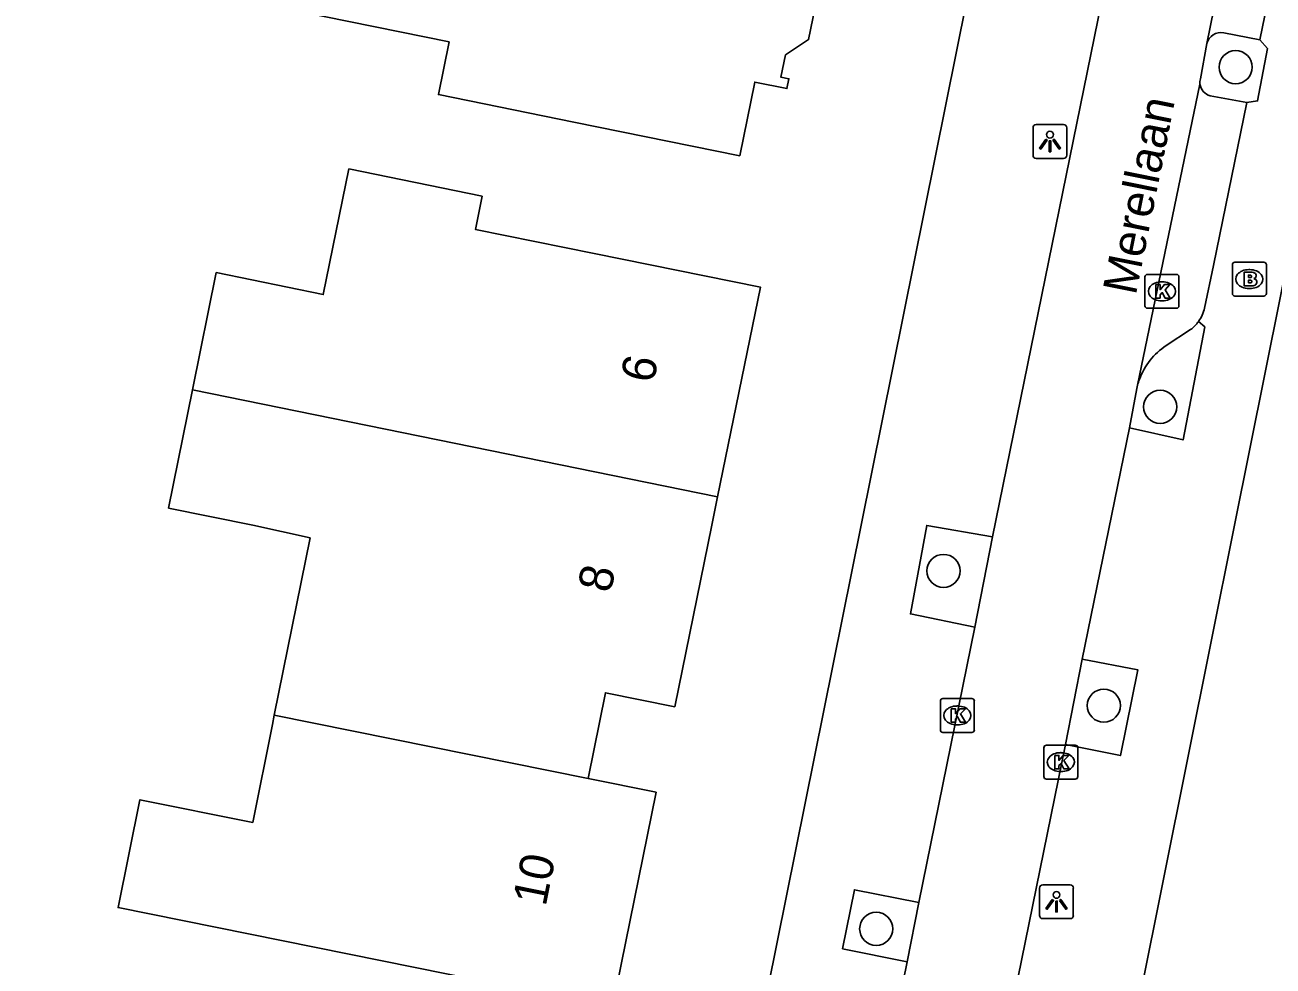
# Model space of a CAD drawing. Extents: x 161772 to 163123, y 383092 to 383917.
# Drawn here: x 162228.47 to 162265.29, y 383736.99 to 383764.76 of the extents above; entities that cross this region are included whole.
import ezdxf

# ---------------------------------------------------------------- set-up
doc = ezdxf.new("R2010")
doc.units = 0
for name, color, linetype in [('IMGEO_Boom', 7, 'Continuous'), ('IMGEO_Brandkraan', 7, 'Continuous'), ('IMGEO_Kolk', 7, 'Continuous'), ('IMGEO_Lichtpunt', 7, 'Continuous'), ('IMGEO_Openbare_ruimte_label', 7, 'Continuous'), ('IMGEO_Pand', 7, 'Continuous'), ('IMGEO_Pand_nummerreeks', 7, 'Continuous'), ('IMGEO_Parkeervlak_open', 7, 'Continuous'), ('IMGEO_Rijbaan_lokaal_open', 7, 'Continuous'), ('IMGEO_Voetpad_open', 7, 'Continuous')]:
    doc.layers.add(name, color=color, linetype=linetype)

msp = doc.modelspace()

# ---------------------------------------------------------------- linework, layer by layer
at = {"layer": 'IMGEO_Boom'}
for centre in [(162264.182, 383763.515), (162261.957, 383753.491), (162255.565, 383748.65), (162260.294, 383744.676), (162253.582, 383738.089)]:
    msp.add_circle(centre, 0.489, dxfattribs=at)
at = {"layer": 'IMGEO_Brandkraan'}
for p, q in [((162264.087, 383756.834), (162264.087, 383757.686)), ((162264.162, 383757.76), (162265.014, 383757.76)), ((162264.575, 383757.54), (162264.6, 383757.54)), ((162265.088, 383757.686), (162265.088, 383756.834)), ((162265.014, 383756.76), (162264.162, 383756.76)), ((162264.598, 383756.98), (162264.573, 383756.98))]:
    msp.add_line(p, q, dxfattribs=at)
for points in [[(162264.087, 383756.834), (162264.087, 383757.686)], [(162264.162, 383757.76), (162265.014, 383757.76)], [(162264.435, 383757.46), (162264.435, 383757.06), (162264.648, 383757.06)], [(162264.666, 383757.46), (162264.435, 383757.46)], [(162265.088, 383757.686), (162265.088, 383756.834)], [(162264.614, 383757.379), (162264.56, 383757.379), (162264.56, 383757.303)], [(162264.56, 383757.303), (162264.613, 383757.303)], [(162264.622, 383757.227), (162264.56, 383757.227), (162264.56, 383757.146)], [(162264.56, 383757.146), (162264.622, 383757.146)], [(162265.014, 383756.76), (162264.162, 383756.76)]]:
    msp.add_lwpolyline(points, dxfattribs=at)
for centre, radius, start, end in [((162264.164, 383757.684), 0.0765, 91.552, 178.448), ((162264.164, 383757.684), 0.0765, 91.552, 178.448), ((162264.67, 383757.315), 0.145, 59.4692, 91.5367), ((162265.012, 383757.684), 0.0765, 1.552, 88.448), ((162265.012, 383757.684), 0.0765, 1.552, 88.448), ((162264.615, 383757.341), 0.0379, 267.8285, 90.9355), ((162264.623, 383757.186), 0.0404, 269.8759, 90.5077), ((162264.695, 383757.362), 0.0922, 285.5137, 58.1501), ((162264.7, 383757.17), 0.105, 301.3115, 78.989), ((162264.164, 383756.836), 0.0765, 181.552, 268.448), ((162264.164, 383756.836), 0.0765, 181.552, 268.448), ((162264.654, 383757.311), 0.251, 268.6676, 293.5347), ((162265.012, 383756.836), 0.0765, 271.552, 358.448), ((162265.012, 383756.836), 0.0765, 271.552, 358.448)]:
    msp.add_arc(centre, radius, start, end, dxfattribs=at)
for centre, major_axis, ratio, start_param, end_param in [((162264.574, 383757.26), (-0.387, 0.002), 0.722429, 4.712389, 7.853982), ((162264.599, 383757.26), (-0.39, 0.002), 0.717154, 1.570796, 4.712389)]:
    msp.add_ellipse(centre, major_axis=major_axis, ratio=ratio, start_param=start_param, end_param=end_param, dxfattribs=at)
at = {"layer": 'IMGEO_Kolk'}
for p, q in [((162261.508, 383756.473), (162261.508, 383757.325)), ((162261.583, 383757.399), (162262.435, 383757.399)), ((162261.996, 383757.179), (162262.021, 383757.179)), ((162262.509, 383757.325), (162262.509, 383756.473)), ((162262.435, 383756.399), (162261.583, 383756.399)), ((162262.019, 383756.619), (162261.994, 383756.619)), ((162255.474, 383743.959), (162255.474, 383744.811)), ((162255.549, 383744.885), (162256.401, 383744.885)), ((162255.962, 383744.665), (162255.987, 383744.665)), ((162256.475, 383744.811), (162256.475, 383743.959)), ((162256.401, 383743.885), (162255.549, 383743.885)), ((162255.985, 383744.105), (162255.96, 383744.105)), ((162258.601, 383743.508), (162259.453, 383743.508)), ((162258.526, 383742.582), (162258.526, 383743.434)), ((162259.014, 383743.288), (162259.039, 383743.288)), ((162259.527, 383743.434), (162259.527, 383742.582)), ((162259.453, 383742.508), (162258.601, 383742.508)), ((162259.037, 383742.728), (162259.012, 383742.728))]:
    msp.add_line(p, q, dxfattribs=at)
for points in [[(162261.508, 383756.473), (162261.508, 383757.325)], [(162261.583, 383757.399), (162262.435, 383757.399)], [(162261.829, 383757.099), (162261.952, 383757.099), (162261.952, 383756.948), (162262.082, 383757.099), (162262.246, 383757.099), (162262.1, 383756.948), (162262.253, 383756.699), (162262.101, 383756.699), (162262.016, 383756.863), (162261.952, 383756.796), (162261.952, 383756.699), (162261.829, 383756.699), (162261.829, 383757.099)], [(162262.509, 383757.325), (162262.509, 383756.473)], [(162262.435, 383756.399), (162261.583, 383756.399)], [(162255.474, 383743.959), (162255.474, 383744.811)], [(162255.549, 383744.885), (162256.401, 383744.885)], [(162255.795, 383744.585), (162255.918, 383744.585), (162255.918, 383744.434), (162256.048, 383744.585), (162256.212, 383744.585), (162256.066, 383744.434), (162256.219, 383744.185), (162256.067, 383744.185), (162255.982, 383744.349), (162255.918, 383744.282), (162255.918, 383744.185), (162255.795, 383744.185), (162255.795, 383744.585)], [(162256.475, 383744.811), (162256.475, 383743.959)], [(162256.401, 383743.885), (162255.549, 383743.885)], [(162258.601, 383743.508), (162259.453, 383743.508)], [(162258.526, 383742.582), (162258.526, 383743.434)], [(162258.847, 383743.208), (162258.97, 383743.208), (162258.97, 383743.057), (162259.1, 383743.208), (162259.264, 383743.208), (162259.118, 383743.057), (162259.271, 383742.808), (162259.119, 383742.808), (162259.034, 383742.972), (162258.97, 383742.905), (162258.97, 383742.808), (162258.847, 383742.808), (162258.847, 383743.208)], [(162259.527, 383743.434), (162259.527, 383742.582)], [(162259.453, 383742.508), (162258.601, 383742.508)]]:
    msp.add_lwpolyline(points, dxfattribs=at)
for centre, start, end in [((162261.585, 383757.323), 91.552, 178.448), ((162261.585, 383757.323), 91.552, 178.448), ((162262.433, 383757.323), 1.552, 88.448), ((162262.433, 383757.323), 1.552, 88.448), ((162261.585, 383756.475), 181.552, 268.448), ((162261.585, 383756.475), 181.552, 268.448), ((162262.433, 383756.475), 271.552, 358.448), ((162262.433, 383756.475), 271.552, 358.448), ((162255.551, 383744.809), 91.552, 178.448), ((162255.551, 383744.809), 91.552, 178.448), ((162256.399, 383744.809), 1.552, 88.448), ((162256.399, 383744.809), 1.552, 88.448), ((162255.551, 383743.961), 181.552, 268.448), ((162255.551, 383743.961), 181.552, 268.448), ((162256.399, 383743.961), 271.552, 358.448), ((162256.399, 383743.961), 271.552, 358.448), ((162258.603, 383743.432), 91.552, 178.448), ((162258.603, 383743.432), 91.552, 178.448), ((162259.451, 383743.432), 1.552, 88.448), ((162259.451, 383743.432), 1.552, 88.448), ((162258.603, 383742.584), 181.552, 268.448), ((162258.603, 383742.584), 181.552, 268.448), ((162259.451, 383742.584), 271.552, 358.448), ((162259.451, 383742.584), 271.552, 358.448)]:
    msp.add_arc(centre, 0.0765, start, end, dxfattribs=at)
for centre, major_axis, ratio, start_param, end_param in [((162261.995, 383756.899), (-0.387, 0.002), 0.722429, 4.712389, 7.853982), ((162262.02, 383756.899), (-0.39, 0.002), 0.717154, 1.570796, 4.712389), ((162255.961, 383744.385), (-0.387, 0.002), 0.722429, 4.712389, 7.853982), ((162255.986, 383744.385), (-0.39, 0.002), 0.717154, 1.570796, 4.712389), ((162259.013, 383743.008), (-0.387, 0.002), 0.722429, 4.712389, 7.853982), ((162259.038, 383743.008), (-0.39, 0.002), 0.717154, 1.570796, 4.712389)]:
    msp.add_ellipse(centre, major_axis=major_axis, ratio=ratio, start_param=start_param, end_param=end_param, dxfattribs=at)
at = {"layer": 'IMGEO_Lichtpunt'}
for p, q in [((162258.207, 383761.724), (162258.207, 383760.917)), ((162258.207, 383761.724), (162258.207, 383760.917)), ((162259.109, 383761.819), (162258.301, 383761.819)), ((162259.109, 383761.819), (162258.301, 383761.819)), ((162259.203, 383760.917), (162259.203, 383761.724)), ((162259.203, 383760.917), (162259.203, 383761.724)), ((162258.301, 383760.823), (162259.109, 383760.823)), ((162258.301, 383760.823), (162259.109, 383760.823)), ((162258.399, 383739.293), (162258.399, 383738.486)), ((162258.399, 383739.293), (162258.399, 383738.486)), ((162259.301, 383739.388), (162258.493, 383739.388)), ((162259.301, 383739.388), (162258.493, 383739.388)), ((162259.395, 383738.486), (162259.395, 383739.293)), ((162259.395, 383738.486), (162259.395, 383739.293)), ((162258.493, 383738.392), (162259.301, 383738.392)), ((162258.493, 383738.392), (162259.301, 383738.392))]:
    msp.add_line(p, q, dxfattribs=at)
for points in [[(162258.581, 383761.388), (162258.62, 383761.36), (162258.432, 383761.098), (162258.394, 383761.125), (162258.581, 383761.388)], [(162258.683, 383761.34), (162258.73, 383761.34), (162258.73, 383761.018), (162258.683, 383761.018), (162258.683, 383761.34)], [(162258.793, 383761.36), (162258.831, 383761.387), (162259.018, 383761.125), (162258.979, 383761.097), (162258.793, 383761.36)], [(162258.773, 383738.957), (162258.812, 383738.929), (162258.624, 383738.667), (162258.586, 383738.694), (162258.773, 383738.957)], [(162258.875, 383738.909), (162258.922, 383738.909), (162258.922, 383738.587), (162258.875, 383738.587), (162258.875, 383738.909)], [(162258.985, 383738.929), (162259.023, 383738.956), (162259.21, 383738.694), (162259.171, 383738.666), (162258.985, 383738.929)]]:
    msp.add_lwpolyline(points, dxfattribs=at)
for centre in [(162258.706, 383761.522), (162258.898, 383739.091)]:
    msp.add_circle(centre, 0.0994, dxfattribs=at)
for centre, start, end in [((162258.301, 383761.724), 90, 180), ((162258.301, 383761.724), 90, 180), ((162259.109, 383761.724), 0, 90), ((162259.109, 383761.724), 0, 90), ((162258.301, 383760.917), 180, 270), ((162258.301, 383760.917), 180, 270), ((162259.109, 383760.917), 270, 0), ((162259.109, 383760.917), 270, 360), ((162258.493, 383739.293), 90, 180), ((162258.493, 383739.293), 90, 180), ((162259.301, 383739.293), 0, 90), ((162259.301, 383739.293), 0, 90), ((162258.493, 383738.486), 180, 270), ((162258.493, 383738.486), 180, 270), ((162259.301, 383738.486), 270, 0), ((162259.301, 383738.486), 270, 360)]:
    msp.add_arc(centre, 0.0946, start, end, dxfattribs=at)
at = {"layer": 'IMGEO_Pand'}
for points in [[(162241.175, 383769.789), (162240.651, 383767.199), (162237.128, 383767.912), (162236.569, 383765.152), (162240.984, 383764.258), (162240.669, 383762.702), (162244.658, 383761.894), (162249.558, 383760.902), (162249.998, 383763.075), (162250.949, 383762.883), (162251.007, 383763.17), (162250.772, 383763.218), (162250.905, 383763.875), (162251.587, 383764.327), (162251.967, 383766.202), (162251.56, 383766.815), (162251.691, 383767.464), (162251.917, 383767.418), (162251.953, 383767.598)], [(162248.902, 383750.832), (162250.166, 383757.024), (162245.266, 383758.016), (162241.757, 383758.727), (162241.957, 383759.706), (162238.028, 383760.509), (162237.272, 383756.805), (162234.113, 383757.45), (162233.413, 383753.99)], [(162233.413, 383753.99), (162232.708, 383750.506), (162235.193, 383750), (162236.883, 383749.623), (162235.828, 383744.395)], [(162233.413, 383753.99), (162248.902, 383750.832)], [(162245.081, 383742.525), (162245.592, 383745.055), (162247.638, 383744.642), (162248.732, 383750), (162248.902, 383750.832)], [(162235.828, 383744.395), (162235.772, 383744.115), (162235.19, 383741.229), (162231.862, 383741.9), (162231.22, 383738.717), (162240.906, 383736.764), (162245.807, 383735.776), (162247.086, 383742.12), (162245.081, 383742.525)], [(162245.081, 383742.525), (162235.828, 383744.395)]]:
    msp.add_lwpolyline(points, dxfattribs=at)
at = {"layer": 'IMGEO_Parkeervlak_open'}
for points in [[(162263.834, 383764.527), (162264.896, 383764.317)], [(162263.434, 383762.671), (162264.516, 383762.469)], [(162262.853, 383755.77), (162262.133, 383755.298)]]:
    msp.add_lwpolyline(points, dxfattribs=at)
for centre, radius, start, end in [((162263.748, 383764.11), 0.425, 78.3237, 166.589), ((162263.526, 383763.057), 0.397, 186.1309, 256.6172), ((162262.205, 383756.64), 1.084, 306.6934, 324.5127), ((162263.272, 383753.585), 2.058, 123.6241, 159.5081), ((162262.803, 383753.735), 1.565, 158.6674, 165.4421)]:
    msp.add_arc(centre, radius, start, end, dxfattribs=at)
at = {"layer": 'IMGEO_Rijbaan_lokaal_open'}
for points in [[(162265.456, 383774.642), (162263.334, 383764.209)], [(162261.67, 383772.531), (162257.015, 383749.655)], [(162263.334, 383764.209), (162263.144, 383763.171)], [(162263.131, 383763.015), (162261.288, 383754.129)], [(162261.288, 383754.129), (162261.267, 383754.035), (162261.054, 383752.871)], [(162259.654, 383746.047), (162261.054, 383752.871)], [(162257.015, 383749.655), (162256.486, 383746.993)], [(162256.486, 383746.993), (162254.837, 383738.866)], [(162259.16, 383743.531), (162259.654, 383746.047)], [(162257.659, 383736.138), (162259.16, 383743.531)], [(162254.837, 383738.866), (162254.497, 383737.116)], [(162254.497, 383737.116), (162251.677, 383723.247)]]:
    msp.add_lwpolyline(points, dxfattribs=at)
msp.add_arc((162263.494, 383763.063), 0.366, 162.882, 187.5907, dxfattribs=at)
at = {"layer": 'IMGEO_Voetpad_open'}
for points in [[(162259.685, 383782.554), (162253.133, 383750), (162236.634, 383668.028), (162228.473, 383628.501)], [(162269.552, 383776.935), (162264.15, 383750), (162255.783, 383708.274)], [(162264.896, 383764.317), (162266.411, 383771.697)], [(162264.516, 383762.469), (162264.828, 383762.517), (162265.126, 383764.062), (162264.896, 383764.317)], [(162263.267, 383756.406), (162263.528, 383757.659), (162264.516, 383762.469)], [(162261.054, 383752.871), (162262.631, 383752.516), (162263.275, 383755.848), (162263.088, 383756.01)], [(162257.015, 383749.655), (162255.07, 383749.991), (162254.589, 383747.382), (162256.486, 383746.993)], [(162259.654, 383746.047), (162261.299, 383745.727), (162260.785, 383743.202), (162259.16, 383743.531)], [(162254.837, 383738.866), (162252.938, 383739.245), (162252.589, 383737.501), (162254.497, 383737.116)]]:
    msp.add_lwpolyline(points, dxfattribs=at)
msp.add_arc((162262.186, 383756.656), 1.11, 324.3869, 346.9653, dxfattribs=at)

# ---------------------------------------------------------------- texts
at = {"layer": 'IMGEO_Openbare_ruimte_label'}
msp.add_text('Merellaan', height=1, rotation=78.6339, dxfattribs=at).set_placement((162261.237, 383756.76))
at = {"layer": 'IMGEO_Pand_nummerreeks'}
for s, rotation, p in [('6', 78.4607, (162247.011, 383754.162)), ('8', 78.4607, (162245.747, 383747.975)), ('10', 78.6015, (162243.831, 383738.728))]:
    msp.add_text(s, height=1, rotation=rotation, dxfattribs=at).set_placement(p)

doc.saveas('drawing.dxf')
